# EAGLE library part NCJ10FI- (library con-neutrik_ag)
Neutrik Audio Connector XLR SERIES Stereo 1/4" jack with switch Source: www.neutrik.com/
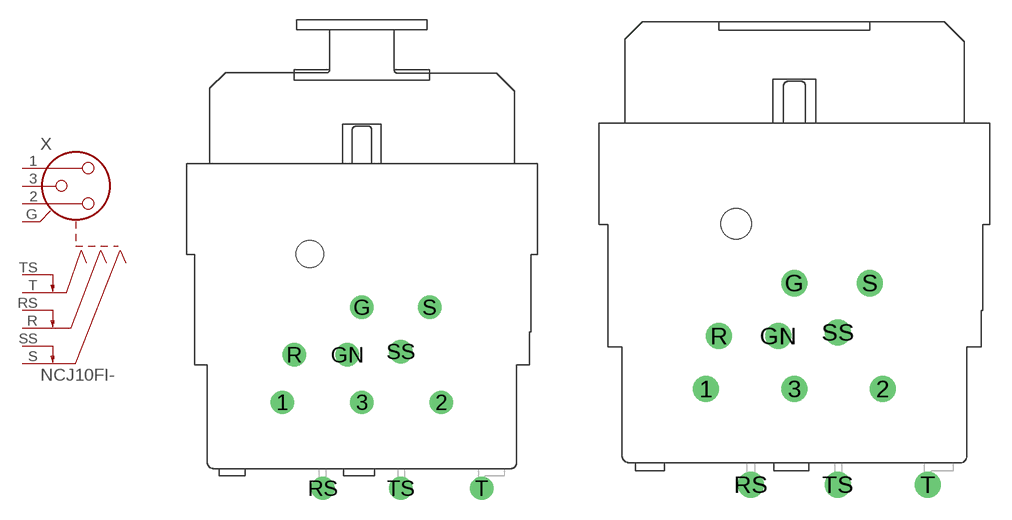
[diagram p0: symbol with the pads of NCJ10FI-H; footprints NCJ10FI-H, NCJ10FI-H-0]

Designator prefix X

## NCJ10FI-H (OC_FARNELL: unknown; OC_NEWARK: unknown)  [NCJ10FI-H]
1  1  pas
2  2  pas
3  3  pas
G  G  pas
R  R  pas
RS  RS  pas
S  S  pas
SS  SS  pas
T  T  pas
TS  TS  pas

## NCJ10FI-H-0 (MPN: NCJ10FI-H-0; OC_FARNELL: unknown; OC_NEWARK: 99B1398)  [NCJ10FI-H-0]
Pads as for NCJ10FI-H

## Footprint NCJ10FI-H (pad centres in mm)
Neutrik Audio Connector combo, 3-pole, female, XLR/switching ground stereo 1/4" jack Source: www.neutrik.com/...210_118401.pdf
drill 1.2 round: 1 -6.1,-18.4; 2 6.1,-18.4; 3 0,-18.4; G 0,-11.1; GN -1.1,-14.75; R -5.2,-14.75; RS -3,-25; S 5.2,-11.1; SS 3,-14.5; T 9.2,-25; TS 3,-25
hole 2.1 at -4,-7

## Footprint NCJ10FI-H-0 (pad centres in mm)
Neutrik Audio Connector combo, 3-pole, female, XLR/switching ground stereo 1/4" jack Source: www.neutrik.com/...210_263081.pdf
drill 1.2 round: 1 -6.1,-18.4; 2 6.1,-18.4; 3 0,-18.4; G 0,-11.1; GN -1.1,-14.75; R -5.2,-14.75; RS -3,-25; S 5.2,-11.1; SS 3,-14.5; T 9.2,-25; TS 3,-25
hole 2.1 at -4,-7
